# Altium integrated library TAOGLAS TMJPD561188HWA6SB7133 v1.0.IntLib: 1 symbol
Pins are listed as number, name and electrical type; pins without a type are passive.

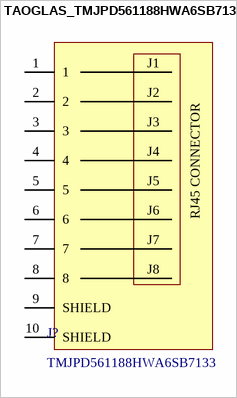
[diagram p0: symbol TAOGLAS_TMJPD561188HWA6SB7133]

## TAOGLAS_TMJPD561188HWA6SB7133
designator J?, comment TMJPD561188HWA6SB7133
1G Base-T Single Port RJ45 without magnetics. Tab-UP with right angle SMT mount; ComponentLibStatus: Created; MFG: Taoglas; Temp_High: +85C; Temp_Low: -40C
footprint TAOGLAS_TMJPD561188HWA6SB7133 (1G Base-T Single Port RJ45 without magnetics. Tab-UP with right angle SMT mount)
pins: 1, 2, 3, 4, 5, 6, 7, 8, 9 SHIELD, 10 SHIELD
